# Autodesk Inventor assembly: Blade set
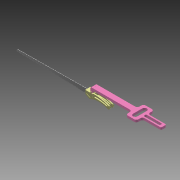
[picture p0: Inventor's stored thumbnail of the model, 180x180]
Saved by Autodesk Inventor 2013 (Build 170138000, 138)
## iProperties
Created: 2008-07
Part Number: Blade set
Document SubType Name: Assembly
Designer: tangg
Mass: 233.304 g
Surface Area: 206.898 cm^2
Volume: 29.7477 cm^3
Density: 7.84277 g/cm^3
Author: tangg
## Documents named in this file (4)
- C:\Users\boganb\Documents\B2 Design\Goodyear\2013 Tutorial Files\Dynamic Simulation 1 and 2\Blade set.iam
- C:\Users\boganb\Documents\B2 Design\Goodyear\2013 Tutorial Files\Dynamic Simulation 1 and 2\Blade clamp.ipt
- C:\Users\boganb\Documents\B2 Design\Goodyear\2013 Tutorial Files\Dynamic Simulation 1 and 2\Saw blade.ipt
- C:\Users\boganb\Documents\B2 Design\Goodyear\2013 Tutorial Files\Dynamic Simulation 1 and 2\Scottish Yoke.ipt
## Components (3 placed, 3 different names)
1. Scottish Yoke:1 — Mate:1, Flush:1
2. Blade clamp:1 — Mate:1, Flush:1, Mate:2, Mate:4
3. Saw blade:1 — Mate:2, Mate:4
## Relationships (4: Mate 3, Flush 1)
- Mate:1: Scottish Yoke:1 ↔ Blade clamp:1
- Flush:1: Scottish Yoke:1 ↔ Blade clamp:1
- Mate:2: Blade clamp:1 ↔ Saw blade:1
- Mate:4: Blade clamp:1 ↔ Saw blade:1
